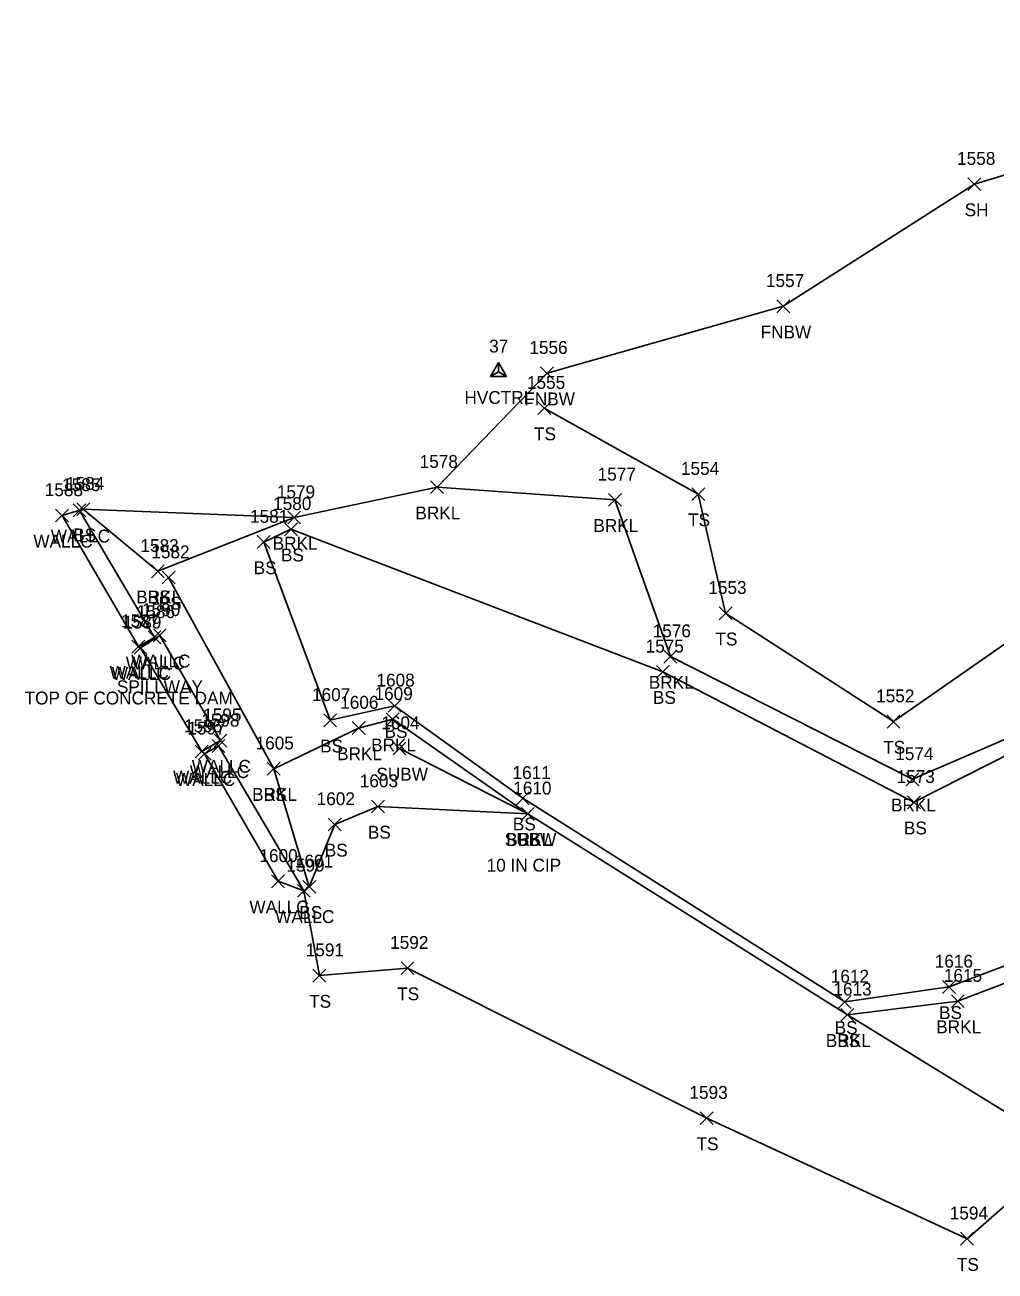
# Model space of a CAD drawing. Extents: x 1754529 to 1755810, y 621660 to 624656.
# Drawn here: x 1754528.9 to 1754679.8, y 624170.8 to 624364.7 of the extents above; entities that cross this region are included whole.
import ezdxf

# ---------------------------------------------------------------- set-up
doc = ezdxf.new("R2010")
doc.units = 0
for name, color, linetype in [('C_A', 7, 'Continuous'), ('C_I', 7, 'Continuous'), ('CPSM', 7, 'Continuous'), ('L_A', 7, 'Continuous'), ('L_C', 7, 'Continuous'), ('L_I', 7, 'Continuous'), ('L_TIC', 7, 'Continuous'), ('LAWE', 7, 'Continuous'), ('LELB', 7, 'Continuous'), ('LSOGP', 7, 'Continuous'), ('LW', 7, 'Continuous'), ('U_A', 7, 'Continuous'), ('U_I', 7, 'Continuous'), ('U_TIC', 7, 'Continuous'), ('UW', 7, 'Continuous')]:
    doc.layers.add(name, color=color, linetype=linetype)

msp = doc.modelspace()

# ---------------------------------------------------------------- linework, layer by layer
at = {"layer": 'CPSM'}
for p, q in [((1754601.35, 624310.03), (1754602.6, 624312.2)), ((1754603.85, 624310.03), (1754602.6, 624312.2)), ((1754602.6, 624310.75), (1754602.6, 624312.2)), ((1754601.35, 624310.03), (1754602.6, 624310.75)), ((1754601.35, 624310.03), (1754603.85, 624310.03)), ((1754602.6, 624310.75), (1754602.6, 624310.75)), ((1754602.6, 624310.75), (1754603.85, 624310.03))]:
    msp.add_line(p, q, dxfattribs=at)
at = {"layer": 'L_TIC'}
for points in [[(1754675.6, 624338.95), (1754677.6, 624340.95)], [(1754677.6, 624338.95), (1754675.6, 624340.95)], [(1754645.87, 624319.94), (1754647.87, 624321.94)], [(1754647.87, 624319.94), (1754645.87, 624321.94)], [(1754609.13, 624309.53), (1754611.13, 624311.53)], [(1754611.13, 624309.53), (1754609.13, 624311.53)], [(1754608.7, 624304.09), (1754610.7, 624306.09)], [(1754610.7, 624304.09), (1754608.7, 624306.09)], [(1754592.02, 624291.79), (1754594.02, 624293.79)], [(1754594.02, 624291.79), (1754592.02, 624293.79)], [(1754632.66, 624290.71), (1754634.66, 624292.71)], [(1754634.66, 624290.71), (1754632.66, 624292.71)], [(1754536.41, 624288.19), (1754538.41, 624290.19)], [(1754538.41, 624288.19), (1754536.41, 624290.19)], [(1754537, 624288.37), (1754539, 624290.37)], [(1754539, 624288.37), (1754537, 624290.37)], [(1754619.69, 624289.83), (1754621.69, 624291.83)], [(1754621.69, 624289.83), (1754619.69, 624291.83)], [(1754533.7, 624287.4), (1754535.7, 624289.4)], [(1754535.7, 624287.4), (1754533.7, 624289.4)], [(1754569.81, 624287.08), (1754571.81, 624289.08)], [(1754571.81, 624287.08), (1754569.81, 624289.08)], [(1754569.31, 624285.24), (1754571.31, 624287.24)], [(1754571.31, 624285.24), (1754569.31, 624287.24)], [(1754565.07, 624283.26), (1754567.07, 624285.26)], [(1754567.07, 624283.26), (1754565.07, 624285.26)], [(1754548.59, 624278.71), (1754550.59, 624280.71)], [(1754550.59, 624278.71), (1754548.59, 624280.71)], [(1754548.59, 624278.71), (1754550.59, 624280.71)], [(1754550.59, 624278.71), (1754548.59, 624280.71)], [(1754550.28, 624277.74), (1754552.28, 624279.74)], [(1754552.28, 624277.74), (1754550.28, 624279.74)], [(1754636.91, 624272.18), (1754638.91, 624274.18)], [(1754638.91, 624272.18), (1754636.91, 624274.18)], [(1754548.92, 624268.74), (1754550.92, 624270.74)], [(1754550.92, 624268.74), (1754548.92, 624270.74)], [(1754545.57, 624266.99), (1754547.57, 624268.99)], [(1754547.57, 624266.99), (1754545.57, 624268.99)], [(1754545.9, 624266.8), (1754547.9, 624268.8)], [(1754547.9, 624266.8), (1754545.9, 624268.8)], [(1754545.9, 624266.8), (1754547.9, 624268.8)], [(1754547.9, 624266.8), (1754545.9, 624268.8)], [(1754548.07, 624268.43), (1754550.07, 624270.43)], [(1754550.07, 624268.43), (1754548.07, 624270.43)], [(1754628.31, 624265.44), (1754630.31, 624267.44)], [(1754630.31, 624265.44), (1754628.31, 624267.44)], [(1754627.15, 624263.07), (1754629.15, 624265.07)], [(1754629.15, 624263.07), (1754627.15, 624265.07)], [(1754585.42, 624257.78), (1754587.42, 624259.78)], [(1754587.42, 624257.78), (1754585.42, 624259.78)], [(1754575.4, 624255.52), (1754577.4, 624257.52)], [(1754577.4, 624255.52), (1754575.4, 624257.52)], [(1754585.13, 624255.68), (1754587.13, 624257.68)], [(1754587.13, 624255.68), (1754585.13, 624257.68)], [(1754663.01, 624255.32), (1754665.01, 624257.32)], [(1754665.01, 624255.32), (1754663.01, 624257.32)], [(1754579.83, 624254.32), (1754581.83, 624256.32)], [(1754581.83, 624254.32), (1754579.83, 624256.32)], [(1754558.04, 624251.54), (1754560.04, 624253.54)], [(1754560.04, 624251.54), (1754558.04, 624253.54)], [(1754558.34, 624252.37), (1754560.34, 624254.37)], [(1754560.34, 624252.37), (1754558.34, 624254.37)], [(1754555.42, 624250.67), (1754557.42, 624252.67)], [(1754557.42, 624250.67), (1754555.42, 624252.67)], [(1754555.42, 624250.67), (1754557.42, 624252.67)], [(1754557.42, 624250.67), (1754555.42, 624252.67)], [(1754555.88, 624250.31), (1754557.88, 624252.31)], [(1754557.88, 624250.31), (1754555.88, 624252.31)], [(1754555.88, 624250.31), (1754557.88, 624252.31)], [(1754557.88, 624250.31), (1754555.88, 624252.31)], [(1754566.62, 624247.99), (1754568.62, 624249.99)], [(1754568.62, 624247.99), (1754566.62, 624249.99)], [(1754566.62, 624247.99), (1754568.62, 624249.99)], [(1754568.62, 624247.99), (1754566.62, 624249.99)], [(1754566.62, 624247.99), (1754568.62, 624249.99)], [(1754568.62, 624247.99), (1754566.62, 624249.99)], [(1754665.98, 624246.34), (1754667.98, 624248.34)], [(1754667.98, 624246.34), (1754665.98, 624248.34)], [(1754582.83, 624242.11), (1754584.83, 624244.11)], [(1754584.83, 624242.11), (1754582.83, 624244.11)], [(1754605.37, 624243.39), (1754607.37, 624245.39)], [(1754607.37, 624243.39), (1754605.37, 624245.39)], [(1754666.2, 624242.77), (1754668.2, 624244.77)], [(1754668.2, 624242.77), (1754666.2, 624244.77)], [(1754606.14, 624240.98), (1754608.14, 624242.98)], [(1754608.14, 624240.98), (1754606.14, 624242.98)], [(1754606.14, 624240.98), (1754608.14, 624242.98)], [(1754608.14, 624240.98), (1754606.14, 624242.98)], [(1754576.11, 624239.32), (1754578.11, 624241.32)], [(1754578.11, 624239.32), (1754576.11, 624241.32)], [(1754567.3, 624230.47), (1754569.3, 624232.47)], [(1754569.3, 624230.47), (1754567.3, 624232.47)], [(1754571.3, 624228.98), (1754573.3, 624230.98)], [(1754573.3, 624228.98), (1754571.3, 624230.98)], [(1754572.16, 624229.62), (1754574.16, 624231.62)], [(1754574.16, 624229.62), (1754572.16, 624231.62)], [(1754572.16, 624229.62), (1754574.16, 624231.62)], [(1754574.16, 624229.62), (1754572.16, 624231.62)], [(1754587.42, 624216.96), (1754589.42, 624218.96)], [(1754589.42, 624216.96), (1754587.42, 624218.96)], [(1754573.73, 624215.8), (1754575.73, 624217.8)], [(1754575.73, 624215.8), (1754573.73, 624217.8)], [(1754671.66, 624214.04), (1754673.66, 624216.04)], [(1754673.66, 624214.04), (1754671.66, 624216.04)], [(1754655.43, 624211.7), (1754657.43, 624213.7)], [(1754657.43, 624211.7), (1754655.43, 624213.7)], [(1754673.02, 624211.83), (1754675.02, 624213.83)], [(1754675.02, 624211.83), (1754673.02, 624213.83)], [(1754655.84, 624209.7), (1754657.84, 624211.7)], [(1754657.84, 624209.7), (1754655.84, 624211.7)], [(1754655.84, 624209.7), (1754657.84, 624211.7)], [(1754657.84, 624209.7), (1754655.84, 624211.7)], [(1754633.97, 624193.63), (1754635.97, 624195.63)], [(1754635.97, 624193.63), (1754633.97, 624195.63)], [(1754674.46, 624174.86), (1754676.46, 624176.86)], [(1754676.46, 624174.86), (1754674.46, 624176.86)]]:
    msp.add_lwpolyline(points, dxfattribs=at)
at = {"layer": 'LAWE'}
for points in [[(1754841.35, 624303.13), (1754816.47, 624310.82), (1754802.72, 624308.73), (1754790.09, 624326.32), (1754761.39, 624331.59), (1754745.82, 624329.48), (1754730.15, 624314.67), (1754719.81, 624307.75), (1754711.15, 624287.95), (1754696.65, 624265.49), (1754683.46, 624254.46), (1754666.98, 624247.34), (1754629.31, 624266.44), (1754620.69, 624290.83), (1754593.02, 624292.79), (1754570.81, 624288.08), (1754549.59, 624279.71)], [(1754567.62, 624248.99), (1754580.83, 624255.32), (1754586.13, 624256.68), (1754607.14, 624241.98), (1754656.84, 624210.7), (1754674.02, 624212.83), (1754716.32, 624229.01), (1754736.35, 624283.47), (1754745.66, 624289.49), (1754751.29, 624285.22), (1754783.8, 624257.95), (1754808.82, 624248.13), (1754842.19, 624225.7)]]:
    msp.add_lwpolyline(points, dxfattribs=at)
at = {"layer": 'LELB'}
for points in [[(1754726.29, 624364.72), (1754707.74, 624342.39), (1754696.89, 624325.13), (1754683, 624292.27), (1754681.82, 624268.72), (1754664.01, 624256.32), (1754637.91, 624273.18), (1754633.66, 624291.71), (1754609.7, 624305.09)], [(1754549.59, 624279.71), (1754538, 624289.37)], [(1754682.61, 624251.63), (1754667.2, 624243.77), (1754628.15, 624264.07), (1754570.31, 624286.24), (1754566.07, 624284.26), (1754576.4, 624256.52), (1754586.42, 624258.78), (1754606.37, 624244.39), (1754656.43, 624212.7), (1754672.66, 624215.04), (1754714.68, 624230.92)], [(1754551.28, 624278.74), (1754567.62, 624248.99)], [(1754573.16, 624230.62), (1754567.62, 624248.99)], [(1754573.16, 624230.62), (1754577.11, 624240.32), (1754583.83, 624243.11), (1754607.14, 624241.98)], [(1754656.84, 624210.7), (1754683.66, 624194.18), (1754718.97, 624215.14), (1754765.47, 624241.5), (1754801.09, 624241), (1754831.12, 624225.89)], [(1754574.73, 624216.8), (1754588.42, 624217.96), (1754634.97, 624194.63), (1754675.46, 624175.86)]]:
    msp.add_lwpolyline(points, dxfattribs=at)
at = {"layer": 'LSOGP'}
msp.add_lwpolyline([(1754698.09, 624346.48), (1754676.6, 624339.95), (1754646.87, 624320.94), (1754610.13, 624310.53), (1754593.02, 624292.79), (1754570.81, 624288.08), (1754538, 624289.37), (1754534.7, 624288.4), (1754546.57, 624267.99), (1754546.9, 624267.8), (1754556.42, 624251.67), (1754556.88, 624251.31), (1754568.3, 624231.47), (1754572.3, 624229.98), (1754574.73, 624216.8), (1754588.42, 624217.96), (1754634.97, 624194.63), (1754675.46, 624175.86), (1754691.8, 624190.17)], dxfattribs=at)
at = {"layer": 'LW'}
for points in [[(1754537.41, 624289.19), (1754549.07, 624269.43), (1754546.57, 624267.99), (1754534.7, 624288.4)], [(1754546.9, 624267.8), (1754549.92, 624269.74), (1754559.34, 624253.37), (1754556.42, 624251.67)], [(1754546.9, 624267.8), (1754556.42, 624251.67)], [(1754556.88, 624251.31), (1754559.04, 624252.54), (1754572.3, 624229.98)], [(1754556.88, 624251.31), (1754568.3, 624231.47)]]:
    msp.add_lwpolyline(points, dxfattribs=at)
at = {"layer": 'U_TIC'}
for points in [[(1754586.18, 624251.14), (1754588.18, 624253.14)], [(1754588.18, 624251.14), (1754586.18, 624253.14)], [(1754606.14, 624240.98), (1754608.14, 624242.98)], [(1754608.14, 624240.98), (1754606.14, 624242.98)]]:
    msp.add_lwpolyline(points, dxfattribs=at)
at = {"layer": 'UW'}
msp.add_lwpolyline([(1754587.18, 624252.14), (1754607.14, 624241.98)], dxfattribs=at)

# ---------------------------------------------------------------- texts
at = {"layer": 'C_A'}
msp.add_text('HVCTRL', height=2, dxfattribs=at).set_placement((1754597.29, 624305.75))
at = {"layer": 'C_I'}
msp.add_text('37', height=2, dxfattribs=at).set_placement((1754601.13, 624313.75))
at = {"layer": 'L_A'}
for s, p in [('SH', (1754675.09, 624334.95)), ('FNBW', (1754643.35, 624315.94)), ('FNBW', (1754606.6, 624305.53)), ('TS', (1754608.11, 624300.09)), ('BRKL', (1754589.66, 624287.79)), ('TS', (1754632.07, 624286.71)), ('WALLC', (1754532.95, 624284.19)), ('BS', (1754536.44, 624284.37)), ('BRKL', (1754617.34, 624285.83)), ('WALLC', (1754530.24, 624283.4)), ('BRKL', (1754567.46, 624283.08)), ('BS', (1754568.75, 624281.24)), ('BS', (1754564.51, 624279.26)), ('BRKL', (1754546.23, 624274.71)), ('BS', (1754548.03, 624274.71)), ('BS', (1754549.73, 624273.74)), ('TS', (1754636.32, 624268.18)), ('WALLC', (1754542.1, 624262.99)), ('WALLC', (1754544.61, 624264.43)), ('WALLC', (1754545.45, 624264.74)), ('WALLC', (1754542.44, 624262.8)), ('WALLC', (1754542.44, 624262.8)), ('BRKL', (1754625.96, 624261.44)), ('BS', (1754626.6, 624259.07)), ('BS', (1754584.86, 624253.78)), ('BS', (1754574.84, 624251.52)), ('BRKL', (1754582.77, 624251.68)), ('TS', (1754662.42, 624251.32)), ('BRKL', (1754577.48, 624250.32)), ('WALLC', (1754554.57, 624247.54)), ('WALLC', (1754554.87, 624248.37)), ('WALLC', (1754551.96, 624246.67)), ('WALLC', (1754551.96, 624246.67)), ('WALLC', (1754552.42, 624246.31)), ('WALLC', (1754552.42, 624246.31)), ('BRKL', (1754564.26, 624243.99)), ('BS', (1754566.06, 624243.99)), ('BS', (1754566.06, 624243.99)), ('BRKL', (1754663.63, 624242.34)), ('BS', (1754582.27, 624238.11)), ('BS', (1754604.81, 624239.39)), ('BS', (1754665.64, 624238.77)), ('BRKL', (1754603.79, 624236.98)), ('BS', (1754605.59, 624236.98)), ('BS', (1754575.56, 624235.32)), ('WALLC', (1754563.84, 624226.47)), ('WALLC', (1754567.84, 624224.98)), ('BS', (1754571.6, 624225.62)), ('BS', (1754571.6, 624225.62)), ('TS', (1754586.83, 624212.96)), ('TS', (1754573.13, 624211.8)), ('BS', (1754671.1, 624210.04)), ('BS', (1754654.87, 624207.7)), ('BRKL', (1754670.67, 624207.83)), ('BRKL', (1754653.49, 624205.7)), ('BS', (1754655.28, 624205.7)), ('TS', (1754633.38, 624189.63)), ('TS', (1754673.87, 624170.86))]:
    msp.add_text(s, height=2, dxfattribs=at).set_placement(p)
at = {"layer": 'L_C'}
for s, p in [('TOP OF CONCRETE DAM', (1754528.87, 624258.99)), ('SPILLWAY', (1754543.23, 624260.74)), ('10 IN CIP', (1754600.74, 624232.98))]:
    msp.add_text(s, height=2, dxfattribs=at).set_placement(p)
at = {"layer": 'L_I'}
for s, p in [('1558', (1754673.91, 624342.95)), ('1557', (1754644.18, 624323.94)), ('1556', (1754607.38, 624313.53)), ('1555', (1754607.01, 624308.09)), ('1578', (1754590.32, 624295.79)), ('1554', (1754630.96, 624294.71)), ('1585', (1754534.72, 624292.19)), ('1584', (1754535.3, 624292.37)), ('1577', (1754618, 624293.83)), ('1588', (1754532.01, 624291.4)), ('1579', (1754568.11, 624291.08)), ('1580', (1754567.53, 624289.24)), ('1581', (1754563.94, 624287.26)), ('1583', (1754546.9, 624282.71)), ('1583', (1754546.9, 624282.71)), ('1582', (1754548.59, 624281.74)), ('1553', (1754635.22, 624276.18)), ('1590', (1754547.14, 624272.74)), ('1587', (1754543.88, 624270.99)), ('1589', (1754544.2, 624270.8)), ('1589', (1754544.2, 624270.8)), ('1586', (1754546.32, 624272.43)), ('1576', (1754626.56, 624269.44)), ('1575', (1754625.46, 624267.07)), ('1608', (1754583.6, 624261.78)), ('1607', (1754573.58, 624259.52)), ('1609', (1754583.3, 624259.68)), ('1552', (1754661.32, 624259.32)), ('1606', (1754577.96, 624258.32)), ('1598', (1754556.35, 624255.54)), ('1595', (1754556.65, 624256.37)), ('1596', (1754553.67, 624254.67)), ('1596', (1754553.67, 624254.67)), ('1597', (1754554.19, 624254.31)), ('1597', (1754554.19, 624254.31)), ('1605', (1754564.8, 624251.99)), ('1605', (1754564.8, 624251.99)), ('1605', (1754564.8, 624251.99)), ('1574', (1754664.29, 624250.34)), ('1611', (1754604.76, 624247.39)), ('1603', (1754581.01, 624246.11)), ('1573', (1754664.5, 624246.77)), ('1610', (1754604.88, 624244.98)), ('1610', (1754604.88, 624244.98)), ('1602', (1754574.3, 624243.32)), ('1600', (1754565.4, 624234.47)), ('1599', (1754569.6, 624232.98)), ('1601', (1754570.91, 624233.62)), ('1601', (1754570.91, 624233.62)), ('1592', (1754585.73, 624220.96)), ('1591', (1754572.6, 624219.8)), ('1616', (1754670.43, 624218.04)), ('1612', (1754654.26, 624215.7)), ('1615', (1754671.85, 624215.83)), ('1613', (1754654.67, 624213.7)), ('1613', (1754654.67, 624213.7)), ('1593', (1754632.28, 624197.63)), ('1594', (1754672.77, 624178.86))]:
    msp.add_text(s, height=2, dxfattribs=at).set_placement(p)
at = {"layer": 'U_A'}
for p in [(1754583.59, 624247.14), (1754603.55, 624236.98)]:
    msp.add_text('SUBW', height=2, dxfattribs=at).set_placement(p)
at = {"layer": 'U_I'}
for s, p in [('1604', (1754584.36, 624255.14)), ('1610', (1754604.88, 624244.98))]:
    msp.add_text(s, height=2, dxfattribs=at).set_placement(p)

doc.saveas('drawing.dxf')
